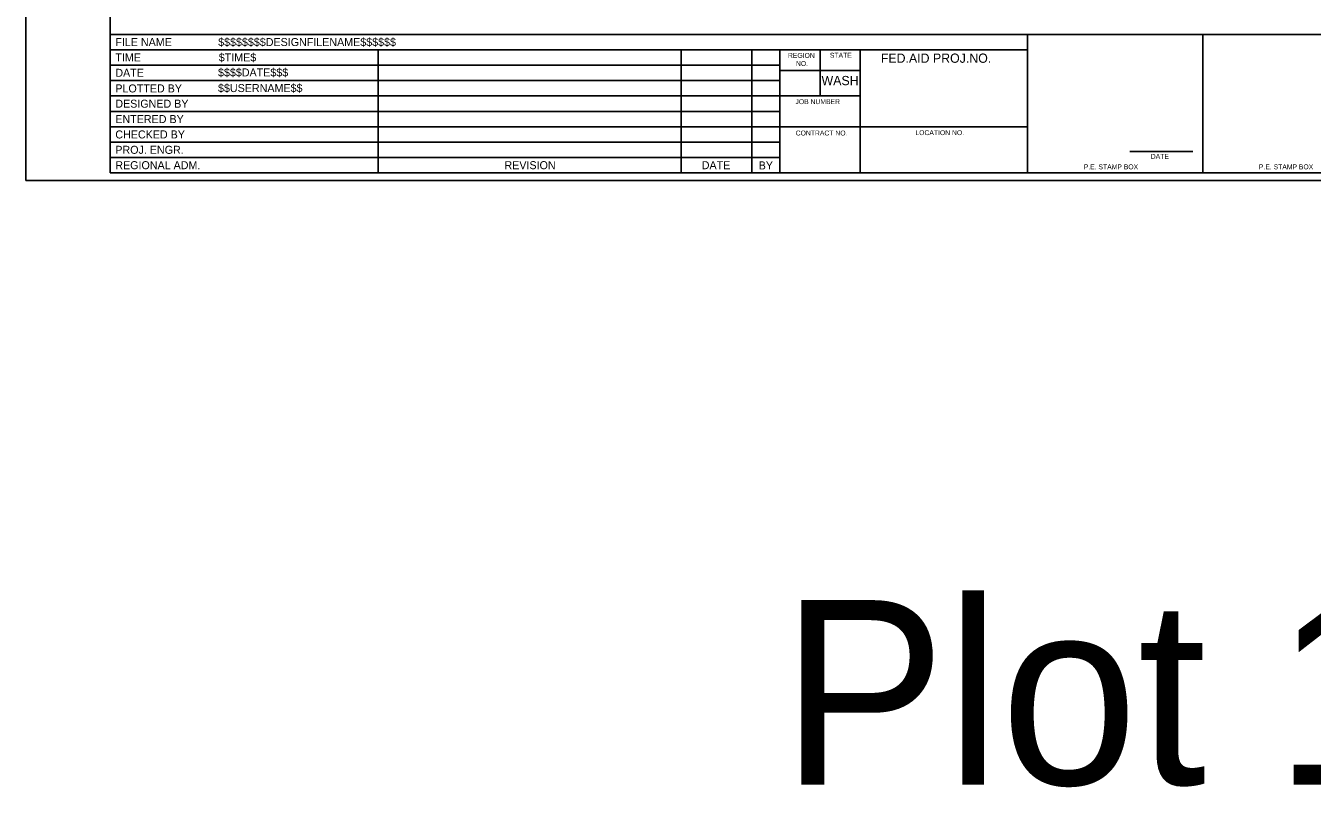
# Model space of a CAD drawing. Extents: x 99988 to 100172, y 99995 to 100047.
# Drawn here: x 99999.31 to 100009.77, y 99995.01 to 100001.2 of the extents above; entities that cross this region are included whole.
import ezdxf

# ---------------------------------------------------------------- set-up
doc = ezdxf.new("R2010")
doc.units = 0
for name, color, linetype in [('SH_GI_PlotLimits', 7, 'Continuous'), ('SH_GI_SheetBorder', 7, 'Continuous'), ('SH_GI_SheetLocationText', 7, 'Continuous'), ('SH_GI_SheetTextInCells', 7, 'Continuous'), ('SH_GI_TitleBlockText', 7, 'Continuous')]:
    doc.layers.add(name, color=color, linetype=linetype)

msp = doc.modelspace()

# ---------------------------------------------------------------- linework, layer by layer
at = {"layer": 'SH_GI_PlotLimits'}
msp.add_lwpolyline([(99999.312, 99999.937), (100015.812, 99999.937), (100015.812, 100010.437), (99999.312, 100010.437)], close=True, dxfattribs=at)
at = {"layer": 'SH_GI_SheetBorder'}
for p, q in [((100000, 100010.375), (100000, 100000)), ((100000, 100001.126), (100015.75, 100001.126)), ((100007.457, 100000), (100007.457, 100001.126)), ((100008.883, 100000), (100008.883, 100001.126)), ((100000, 100001.001), (100007.457, 100001.001)), ((100002.179, 100001.001), (100002.179, 100000)), ((100004.641, 100001.001), (100004.641, 100000)), ((100005.216, 100001.001), (100005.216, 100000)), ((100005.445, 100001.001), (100005.445, 100000)), ((100005.772, 100000.625), (100005.772, 100001.001)), ((100006.096, 100000), (100006.096, 100001.001)), ((100000, 100000.876), (100002.182, 100000.876)), ((100002.182, 100000.876), (100005.447, 100000.876)), ((100006.096, 100000.831), (100005.447, 100000.831)), ((100000, 100000.751), (100002.182, 100000.751)), ((100002.182, 100000.751), (100005.447, 100000.751)), ((100000, 100000.625), (100005.447, 100000.625)), ((100006.096, 100000.625), (100005.447, 100000.625)), ((100000, 100000.5), (100005.447, 100000.5)), ((100000, 100000.375), (100005.447, 100000.375)), ((100007.457, 100000.375), (100005.447, 100000.375)), ((100000, 100000.25), (100005.447, 100000.25)), ((100008.29, 100000.173), (100008.802, 100000.173)), ((100000, 100000.125), (100005.447, 100000.125)), ((100000, 100000), (100015.75, 100000))]:
    msp.add_line(p, q, dxfattribs=at)

# ---------------------------------------------------------------- texts
at = {"layer": 'SH_GI_SheetLocationText'}
msp.add_text('Plot 1', height=1.5, dxfattribs=at).set_placement((100005.455, 99995.027))
at = {"layer": 'SH_GI_SheetTextInCells'}
for s, height, p in [('FILE NAME', 0.0651, (100000.041, 100001.031)), ('TIME', 0.0651, (100000.041, 100000.906)), ('REGION', 0.04, (100005.51, 100000.935)), ('NO.', 0.04, (100005.575, 100000.869)), ('STATE', 0.04, (100005.851, 100000.936)), ('FED.AID PROJ.NO.', 0.07506, (100006.265, 100000.895)), ('DATE', 0.0651, (100000.041, 100000.781)), ('WASH', 0.0751, (100005.783, 100000.713)), ('PLOTTED BY', 0.0651, (100000.041, 100000.654)), ('DESIGNED BY', 0.06505, (100000.041, 100000.53)), ('JOB NUMBER', 0.04, (100005.571, 100000.559)), ('ENTERED BY', 0.0651, (100000.041, 100000.405)), ('CHECKED BY', 0.0651, (100000.041, 100000.28)), ('CONTRACT NO.', 0.04003, (100005.573, 100000.304)), ('LOCATION NO.', 0.04003, (100006.546, 100000.307)), ('PROJ. ENGR.', 0.06505, (100000.041, 100000.155)), ('DATE', 0.04, (100008.46, 100000.114)), ('REGIONAL ADM.', 0.06505, (100000.041, 100000.03)), ('REVISION', 0.0651, (100003.205, 100000.03)), ('DATE', 0.0651, (100004.809, 100000.03)), ('BY', 0.0651, (100005.272, 100000.028)), ('P.E. STAMP BOX', 0.04003, (100007.915, 100000.029)), ('P.E. STAMP BOX', 0.04003, (100009.339, 100000.029))]:
    msp.add_text(s, height=height, dxfattribs=at).set_placement(p)
at = {"layer": 'SH_GI_TitleBlockText'}
for s, height, p in [('$$$$$$$$DESIGNFILENAME$$$$$$', 0.06505, (100000.877, 100001.031)), ('$TIME$', 0.0651, (100000.882, 100000.906)), ('$$$$DATE$$$', 0.06505, (100000.876, 100000.784)), ('$$USERNAME$$', 0.06505, (100000.876, 100000.657))]:
    msp.add_text(s, height=height, dxfattribs=at).set_placement(p)

doc.saveas('drawing.dxf')
